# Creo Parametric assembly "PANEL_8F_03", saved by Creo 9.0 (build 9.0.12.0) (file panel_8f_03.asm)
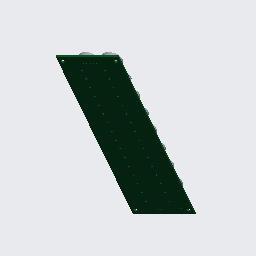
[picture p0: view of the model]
Units: millimeter Newton Second (mmNs); MM, TONNE, SECS

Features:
  1. coordinate system "PANEL_8F_03"
  2. imported feature "Import Feature id 4"
  3. component "PCB_8F"
  4. component "TX_8F_T1"
  5. component "TX_8F_T1"
  6. component "TX_8F_T1"
  7. component "TX_8F_T1"
  8. component "TX_8F_T1"
  9. component "TX_8F_T1"
  10. component "TX_8F_T1"
  11. component "TX_8F_T1"
  12. component "TX_8F_T1"
  13. component "TX_8F_T1"
  14. component "TX_8F_T1"
  15. component "TX_8F_T1"
  16. component "TX_8F_T1"
  17. component "TX_8F_T1"
  18. component "TX_8F_T1"
  19. component "TX_8F_T1"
